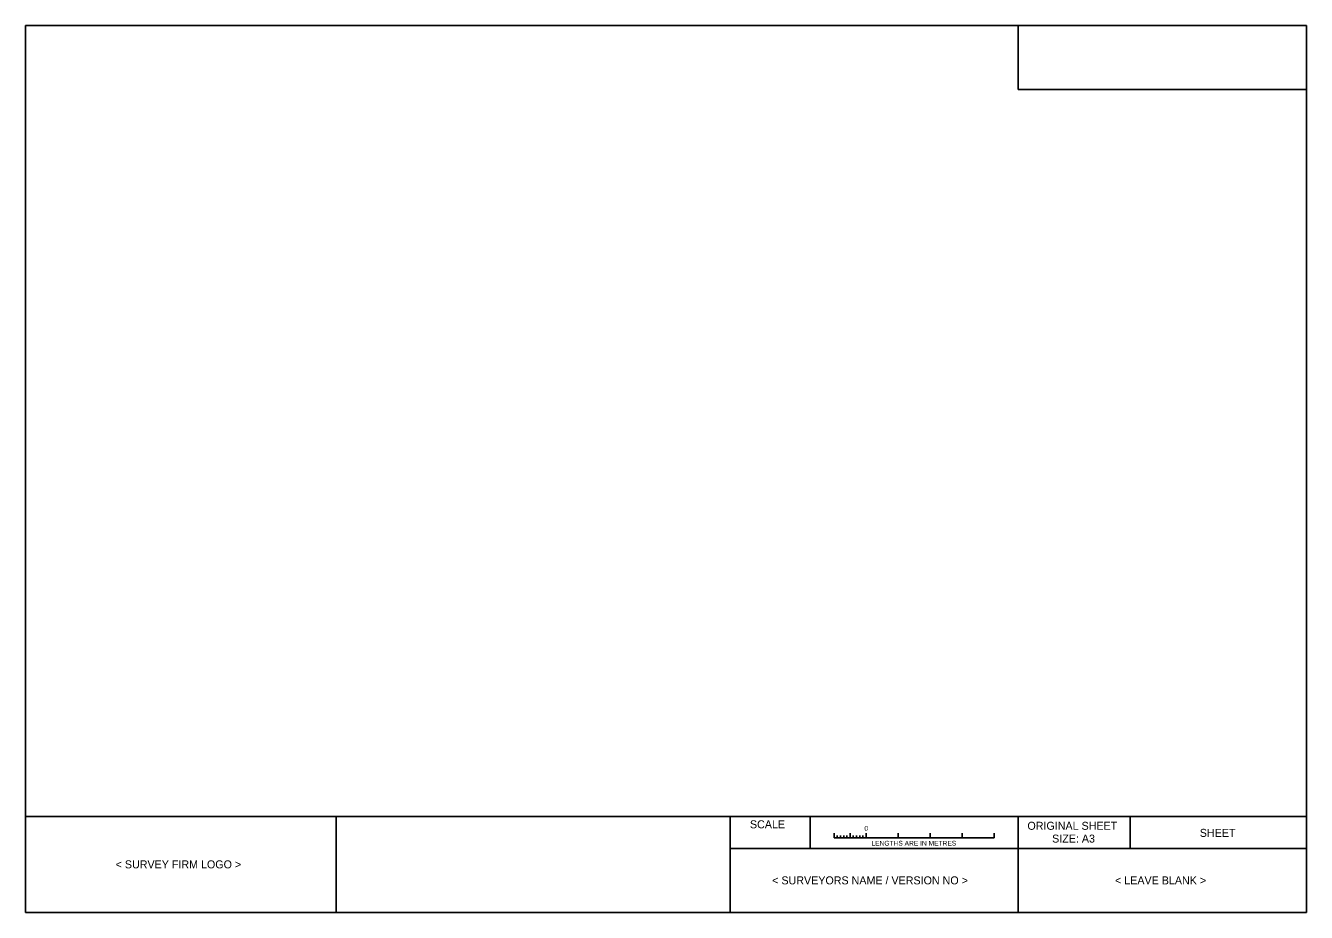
# Model space of a CAD drawing. Extents: x 0.01 to 0.41, y 0.01 to 0.287.
import ezdxf

# ---------------------------------------------------------------- set-up
doc = ezdxf.new("R2010")
doc.units = 0
for name, color, linetype in [('Proforma major line', 7, 'Continuous'), ('Proforma minor line', 7, 'Continuous'), ('Proforma text', 7, 'Continuous'), ('Scale', 7, 'Continuous')]:
    doc.layers.add(name, color=color, linetype=linetype)

msp = doc.modelspace()

# ---------------------------------------------------------------- linework, layer by layer
at = {"layer": 'Proforma major line'}
for p, q in [((0.01, 0.01), (0.01, 0.287)), ((0.41, 0.287), (0.01, 0.287)), ((0.41, 0.01), (0.41, 0.287)), ((0.01, 0.04), (0.41, 0.04)), ((0.01, 0.01), (0.41, 0.01))]:
    msp.add_line(p, q, dxfattribs=at)
at = {"layer": 'Proforma minor line'}
for p, q in [((0.32, 0.287), (0.32, 0.267)), ((0.32, 0.267), (0.41, 0.267)), ((0.01, 0.04), (0.107, 0.04)), ((0.107, 0.04), (0.107, 0.01)), ((0.23, 0.04), (0.23, 0.01)), ((0.255, 0.03), (0.255, 0.04)), ((0.32, 0.04), (0.32, 0.01)), ((0.355, 0.03), (0.355, 0.04)), ((0.23, 0.03), (0.32, 0.03)), ((0.32, 0.03), (0.41, 0.03))]:
    msp.add_line(p, q, dxfattribs=at)
at = {"layer": 'Scale'}
for p, q in [((0.2625, 0.03324), (0.2625, 0.03474)), ((0.3125, 0.03324), (0.2625, 0.03324)), ((0.2635, 0.03399), (0.2635, 0.03324)), ((0.2645, 0.03399), (0.2645, 0.03324)), ((0.2655, 0.03399), (0.2655, 0.03324)), ((0.2665, 0.03399), (0.2665, 0.03324)), ((0.2675, 0.03474), (0.2675, 0.03324)), ((0.2685, 0.03399), (0.2685, 0.03324)), ((0.2695, 0.03399), (0.2695, 0.03324)), ((0.2705, 0.03399), (0.2705, 0.03324)), ((0.2715, 0.03399), (0.2715, 0.03324)), ((0.2725, 0.03324), (0.2725, 0.03474)), ((0.2825, 0.03324), (0.2825, 0.03474)), ((0.2925, 0.03324), (0.2925, 0.03474)), ((0.3025, 0.03324), (0.3025, 0.03474)), ((0.3125, 0.03324), (0.3125, 0.03474))]:
    msp.add_line(p, q, dxfattribs=at)

# ---------------------------------------------------------------- texts
at = {"layer": 'Proforma text'}
for s, p in [('SCALE', (0.23622, 0.03626)), ('ORIGINAL SHEET', (0.32288, 0.0358)), ('SHEET', (0.37672, 0.03359)), ('SIZE: A3', (0.33059, 0.0318)), ('< SURVEY FIRM LOGO >', (0.03812, 0.02375)), ('< SURVEYORS NAME / VERSION NO >', (0.24317, 0.01875)), ('< LEAVE BLANK >', (0.35025, 0.01875))]:
    msp.add_text(s, height=0.0025, dxfattribs=at).set_placement(p)
at = {"layer": 'Scale'}
for s, p in [('0', (0.27197, 0.03552)), ('LENGTHS ARE IN METRES', (0.27417, 0.03085))]:
    msp.add_text(s, height=0.0015, dxfattribs=at).set_placement(p)

doc.saveas('drawing.dxf')
